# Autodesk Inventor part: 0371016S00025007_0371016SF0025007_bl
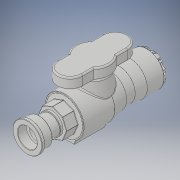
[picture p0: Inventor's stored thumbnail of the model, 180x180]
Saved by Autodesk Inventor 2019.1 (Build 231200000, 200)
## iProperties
Created: 2022-04
Part Number: 0371016S00025007_0371016SF0025007_bl
Material: Generic
Description: PA Ball Valve Series 1 25mm x Free Nut Female 3/4''
Document SubType Name: Modeling
Designer: Lenora
Density: 1 g/cm^3
Appearance: Default
Author: Lenora
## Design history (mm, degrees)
derived "0371016.ipt"
feature "Solid1::0371016.ipt" dims "ScaleForDerivedMember" = 10
tag "TaggingFeature1"
body "Solid1"
other parameters: "d0" = 171 [user parameter], "d16" = 82.08 [user parameter], "d19" = 1 [user parameter], "d20" = 42.75 [user parameter], "d22" = 85 deg [user parameter], "d25" = 1 [user parameter], "d34" = 30.78 [user parameter], "d35" = 17.1 [user parameter], "d37" = 0 [user parameter], "d39" = 360 deg [user parameter], "d43" = 27 [user parameter], "d45" = 70 deg [user parameter], "d46" = 70 deg [user parameter], "d48" = 0 [user parameter], "d57" = 2 [user parameter], "d63" = 53 [user parameter], "d71" = 8.55 [user parameter], "d72" = 12.825 [user parameter], "d73" = 30.78 [user parameter], "d76" = 54 [user parameter], "d77" = 16.2 [user parameter], "d78" = 46.17 [user parameter], "d79" = 21.375 [user parameter], "d80" = 100 deg [user parameter], "d81" = 14.535 [user parameter], "d83" = 22.95 [user parameter], "d84" = 12.825 [user parameter], "d85" = 26.5 [user parameter], "d90" = 0 [user parameter], "d91" = 7.95 [user parameter], "d92" = 45 deg [user parameter], "d93" = 4.24 [user parameter], "d94" = 1.696 [user parameter], "d95" = 2.12 [user parameter], "d96" = 2.12 [user parameter], "d97" = 2.12 [user parameter], "d98" = 2.12 [user parameter], "d111" = 0.5 [user parameter], "d112" = 2 [user parameter], "d114" = 7.42 [user parameter], "d115" = 0 [user parameter], "d117" = 360 deg [user parameter], "d119" = 42.93 [user parameter], "d120" = 47 [user parameter], "d121" = 25 [user parameter], "d122" = 1 [user parameter], "d123" = 89 deg [user parameter], "d124" = 80 deg [user parameter], "d125" = 36 [user parameter], "d127" = 15.2 [user parameter], "d132" = 49.29 [user parameter], "d134" = 0 [user parameter], "d140" = 26.441 [user parameter], "d141" = 18.5087 [user parameter], "d142" = 11.97 [user parameter], "d144" = 36 [user parameter], "d145" = 11.97 [user parameter], "d146" = 4.275 [user parameter], "d147" = 29.0851 [user parameter], "d148" = 17.1 [user parameter], "d149" = 34.2 [user parameter], "d150" = 30.78 [user parameter], "d153" = 19 [user parameter], "d155" = 0.5 [user parameter], "d" = 25 [user parameter], "A1" = 27 [user parameter], "A2" = 54 [user parameter], "H_" = 171 [user parameter], "E_" = 53 [user parameter], "E1" = 47 [user parameter], "B" = 36 [user parameter], "l2" = 19 [user parameter], "G" = 26.441 [user parameter]
